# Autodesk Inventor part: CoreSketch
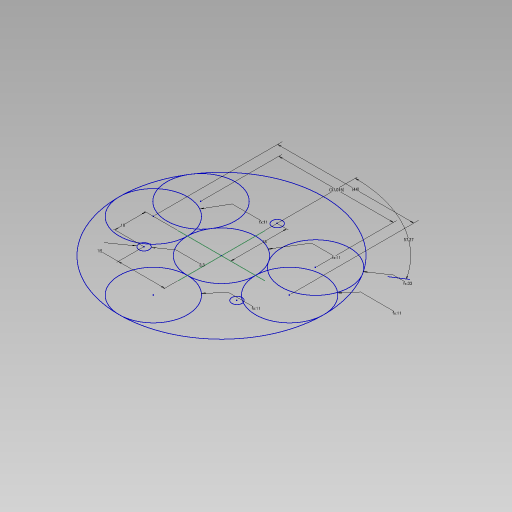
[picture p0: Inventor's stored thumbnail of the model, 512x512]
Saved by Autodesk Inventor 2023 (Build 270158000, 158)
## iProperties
Created: 2024-05
Part Number: CoreSketch
Material: 一般
Document SubType Name: Modeling
Designer: kumagai
Density: 1 g/cm^3
Appearance: 既定
Author: kumagai
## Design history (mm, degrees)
sketch "PlanetaryGears"
  geometry: L1 (0, -14)-(0, 14) reference; L2 (-14, 0)-(14, 0) reference; L3 (-32.742, -21.042)-(-37.024, -23.794); C1 r 33 at (0, 0); C2 r 11 at (0, 0); C3 r 11 at (22, 0); C4 r 11 at (-22, 0); C5 r 11 at (0, 22); C6 r 11 at (-18.508, -11.894); C7 r 11 at (18.508, -11.894); C8 r 1.65 at (15, 10); C9 r 1.65 at (-15, 10); C10 r 1.65 at (0, -18); 1 further point
  constraints: 10 centre point, 8 equal radius, 6 point on line, 2 coincident, 2 end point, 1 symmetric about line, 1 other
  dimensions: "d1" = 33 radius of C1 (= 3 x PR); "d2" = 11 radius of C2 (= PR); "d3" = 11 radius of C4 (= PR); "d4" = 11 radius of C3 (= PR); "d5" = 11 radius of C5 (= PR); "d6" = 44 distance of C4.centre C3.centre (derived); "d9" = 37.01516 distance of C7.centre C6.centre (derived); "d98" = 15 distance from line of C8.centre L1; "d99" = 10 distance from line of C8.centre L2; "d100" = 3.3 diameter of C8; "d101" = 18 distance from line of C10.centre L2; "d104" = 57.2727 deg angle of L3 L1
sketch "Vertical"
  geometry: L1 (0, 65.337)-(0, -65.337) reference; L2 (-46.2, 0)-(46.2, 0) reference; L3 (-11, 2)-(11, 2); L4 (11, 2)-(11, -2); L5 (11, -2)-(-11, -2); L6 (-11, -2)-(-11, 2); L7 (11, 2)-(33, 2); L8 (33, 2)-(33, -2); L9 (33, -2)-(11, -2); L10 (11, -2)-(11, 2); L11 (22, 2.772)-(22, -2.683); L12 (-33, 2)-(-11, 2); L13 (-11, 2)-(-11, -2); L14 (-11, -2)-(-33, -2); L15 (-33, -2)-(-33, 2); L16 (-22, 4.087)-(-22, -4.199); L17 (-33, 10)-(-11, 10); L18 (-11, 10)-(-11, 6); L19 (-11, 6)-(-33, 6); L20 (-33, 6)-(-33, 10); L21 (-27.353, 10)-(-16.647, 10); L22 (-16.647, 10)-(-16.647, 16); L23 (-16.647, 16)-(-27.353, 16); L24 (-27.353, 16)-(-27.353, 10); L25 (11, 16)-(33, 16); L26 (33, 16)-(33, 12); L27 (33, 12)-(11, 12); L28 (11, 12)-(11, 16); L29 (16.134, 12)-(27.866, 12); L30 (27.866, 12)-(27.866, 6); L31 (27.866, 6)-(16.134, 6); L32 (16.134, 6)-(16.134, 12); L33 (-22, 18.272)-(-22, 9.031); L34 (22, 22.635)-(22, 12.71); L35 (33, -2)-(35, -2); L36 (35, -2)-(35, 10); L37 (35, 10)-(33, 10); L38 (33, 10)-(33, -2); L39 (0, -4)-(37.5, -4); L40 (40.5, -1)-(40.5, 14); L41 (43.9, -8)-(0, -8); L42 (0, -4)-(0, -8); L43 (35, -2)-(39, -2); L44 (39, -2)-(39, 3.066); L45 (38.45, 8.685)-(41.471, 10.429); L46 (38.45, 10)-(35, 10); L47 (40.5, 9.627)-(41.993, 8.375); L48 (41.55, 3.315)-(40.5, 2.709); L49 (37.5, -4)-(40.5, -1); L50 (-43, 43.294)-(-1, 43.294); L51 (-1, 43.294)-(-1, 26); L52 (-1, 26)-(-43, 26); L53 (-43, 26)-(-43, 43.294); L54 (1, 43.294)-(43, 43.294); L55 (43, 43.294)-(43, 26); L56 (43, 26)-(1, 26); L57 (1, 26)-(1, 43.294); L58 (-22, 45.556)-(-22, 31.232); L59 (22, 47.214)-(22, 32.287); L60 (48, 5.268)-(48, -2.616); L61 (43.6, -11)-(54, -11); L62 (54, -11)-(54, 18); L63 (45.222, -3.461)-(46.5, -2.566); L64 (48, -2.616)-(49.192, -3.808)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; A1 r 3.1 centre (40, 6) between (39, 3.066) and (38.45, 8.685); A2 r 3.1 centre (47, -6) between (45.222, -3.461) and (49.192, -3.808); A3 r 3.1 centre (47, 13) between (43.9, 13) and (49, 10.631); 2 further points; 1 other entity
  constraints: 177 end point, 17 collinear, 17 point on line, 15 vertical, 13 point on circle, 11 horizontal, 8 tangent, 3 centre point, 3 parallel, 14 other
  dimensions: "d10" = 11 distance between parallel lines of L4 L1 (= PR); "d11" = 4 distance between parallel lines of L5 L3 (= GTH); "d12" = 11 distance between parallel lines of L10 L11 (= PR); "d13" = 11 distance between parallel lines of L16 L13 (= PR); "d14" = 4 distance between parallel lines of L19 L17 (= GTH); "d15" = 6 distance between parallel lines of L17 L23 (= BTH); "d16" = 6 distance between parallel lines of L31 L29 (= BTH); "d17" = 4 distance between parallel lines of L27 L25 (= GTH); "d19" = 11 distance between parallel lines of L33 L20 (= PR); "d20" = 11 distance between parallel lines of L34 L28 (= PR); "d21" = 33 distance between parallel lines of L1 L38 (= 3 x PR); "d22" = 2 distance between parallel lines of L38 L36 (= 2 x module); "d23" = 2 distance between parallel lines of L5 L39; "d24" = 4 distance between parallel lines of L41 L39; "d25" = 7 distance from line of L38 A1.centre; "d27" = 6.2 diameter of A1 (= BBR); "d28" = 14 distance between parallel lines of L3 L25; "d29" = 30 deg angle of L46 L45; "d30" = 1 distance from line of A1.centre L44; "d31" = 0.5 distance from line of L40 A1.centre; "d32" = 130 deg angle of L40 L47; "d33" = 120 deg angle of L40 L48; "d34" = 6.2 diameter of A3 (= BBR); "d35" = 6.2 diameter of A2 (= BBR); "d36" = 45 deg angle of L40 L49; "d37" = 3 horizontal distance of L39.end L40.start; "d40" = 42 distance between parallel lines of L51 L53 (= MSQ); "d41" = 42 distance between parallel lines of L55 L57 (= MSQ); "d42" = 21 distance between parallel lines of L62 L38; "d43" = 54 distance between parallel lines of L62 L1 (derived); "d44" = 6 distance between parallel lines of L38 L44 (derived); "d45" = 4 distance from line of A2.centre L9; "d46" = 14 distance from line of A2.centre L38; "d51" = 135 deg angle of L60 L64; "d53" = 13.5 distance between parallel lines of L38 L65; "d54" = 125 deg angle of L63 L65; "d55" = 6 distance between parallel lines of L65 L40 (derived); "d57" = 15 distance between parallel lines of L38 L60; "d58" = 0.3 distance from line of A2.centre L66; "d59" = 135 deg angle of L67 L66; "d61" = 0.3 distance from line of A2.centre L69; "d62" = 10 distance between parallel lines of L70 L8; "d63" = 5 distance from line of L61 A2.centre; "d64" = 0.6 distance between parallel lines of L70 L67; "d66" = 14 distance from line of L38 A3.centre; "d67" = 6 distance between parallel lines of L62 L60 (derived); "d68" = 45 deg angle of L60 L72; "d69" = 20 distance between parallel lines of L56 L31; "d73" = 1 distance from line of A3.centre L77; "d74" = 2 distance from line of A3.centre L79; "d75" = 30 deg angle of L65 L80; "d76" = 4 vertical distance of L79.end A3.centre; "d77" = 1 distance between parallel lines of L76 L80; "d78" = 4 distance from line of L73 A3.centre; "d79" = 45 deg angle of L73 L74; "d81" = 1 distance between parallel lines of L79 L75; "d82" = 1.5 vertical distance of L73.end A3.centre; "d83" = 1 distance from line of A3.centre L82; "d84" = 2 distance between parallel lines of L83 L25; "d85" = 8 distance between parallel lines of L83 L56 (derived); "d86" = 6 distance between parallel lines of L73 L85; "d88" = 4.5 distance from line of A3.centre L87; "d89" = 4.4 distance from line of A3.centre L86; "d90" = 12 distance of L35.end L36.end (derived)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
sketch "OuterLayout"
  geometry: L1 (0, -46.2)-(0, 46.2) reference; L2 (-73.4, 0)-(62.4, 0) reference; L3 (43, -21)-(1, -21); L4 (1, -21)-(1, 21); L5 (1, 21)-(43, 21); L6 (43, 21)-(43, -21); L7 (-1, -21)-(-43, -21); L8 (-43, -21)-(-43, 21); L9 (-43, 21)-(-1, 21); L10 (-1, 21)-(-1, -21); C1 r 11.1 at (22, 0); C2 r 11.1 at (-22, 0); C3 r 2.5 at (-22, 0); C4 r 2.5 at (22, 0); C5 r 1.6 at (-6.5, -15.5); C6 r 1.6 at (-37.5, -15.5); C7 r 1.6 at (-6.5, 15.5); C8 r 1.6 at (-37.5, 15.5); C9 r 51.5 at (0, 0); C10 r 1.65 at (-57, 0); A1 r 54 centre (0, 0) between (-53.229, -9.091) and (-53.229, 9.091); A2 r 5 centre (-58.158, -9.933) between (-53.229, -9.091) and (-57.579, -4.966); A3 r 5 centre (-58.158, 9.933) between (-57.579, 4.966) and (-53.229, 9.091); A4 r 5 centre (-57, 0) between (-53.86, 3.891) and (-53.86, -3.891); 1 further point
  constraints: 16 end point, 14 centre point, 12 point on circle, 5 coincident, 4 equal radius, 4 tangent, 3 point on line, 2 collinear, 2 horizontal alignment, 2 vertical, 2 vertical alignment, 1 horizontal, 5 other
  dimensions: "d105" = 22.2 diameter of C2; "d106" = 5 diameter of C3; "d107" = 21 distance from line of L10 C2.centre (derived); "d108" = 42 distance between parallel lines of L8 L10; "d109" = 21 distance from line of L8 C2.centre (derived); "d110" = 42 distance between parallel lines of L9 L7; "d111" = 44 distance of C1.centre C2.centre; "d112" = 15.5 horizontal distance of C7.centre C2.centre (derived); "d113" = 31 distance of C8.centre C7.centre; "d114" = 3.2 diameter of C8; "d115" = 15.5 horizontal distance of C8.centre C2.centre (derived); "d116" = 31 distance of C8.centre C6.centre (derived); "d117" = 15.5 horizontal distance of C2.centre C6.centre (derived); "d118" = 15.5 horizontal distance of C8.centre C3.centre (derived); "d121" = 54 radius of A1; "d122" = 51.5 radius of C9; "d123" = 57 distance from line of L1 C10.centre; "d124" = 3.3 diameter of C10; "d126" = 5 radius of A2; "d127" = 5 radius of A4
other parameters: "module" = 1 [user parameter; used in 2 equation terms], "PR" = 11 (computed from module, NT) [user parameter; used in 11 equation terms], "GTH" = 4 [user parameter; used in 3 equation terms], "BTH" = 6 [user parameter; used in 2 equation terms], "BBR" = 6.2 [user parameter; used in 3 equation terms], "d39" = 5.5 (derived), "MSQ" = 42 [user parameter; used in 2 equation terms], "d47" = 150 deg, "d50" = 120 deg, "d52" = 13
